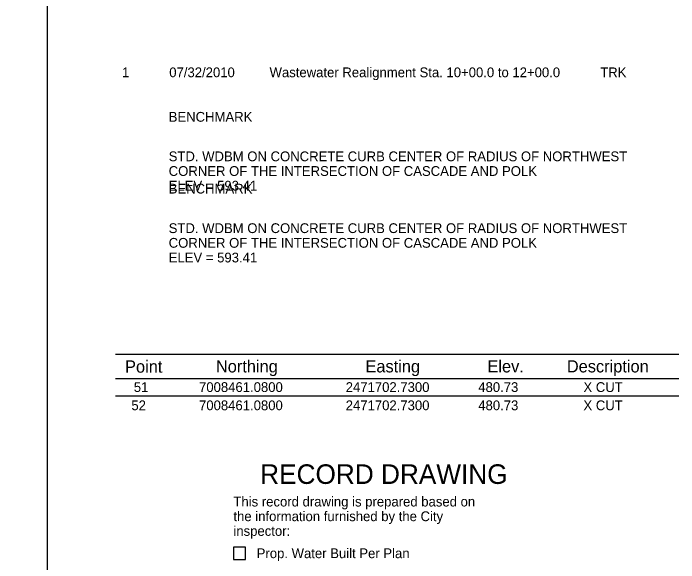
# Model space of a CAD drawing. Extents: x -3875 to -2152, y -2513 to -1536.
# Drawn here: x -2468.5 to -2196.8, y -2281.1 to -2056.6 of the extents above; entities that cross this region are included whole.
import ezdxf

# ---------------------------------------------------------------- set-up
doc = ezdxf.new("R2010")
doc.units = 0
for name, color, linetype in [('G_BORDER', 7, 'Continuous'), ('G_SHEET_EDGE', 7, 'Continuous'), ('G_SIGNATURE BLOCK', 7, 'Continuous')]:
    doc.layers.add(name, color=color, linetype=linetype)

msp = doc.modelspace()

# ---------------------------------------------------------------- linework, layer by layer
at = {"layer": 'G_BORDER'}
for p, q in [((-2426.83, -2195.84), (-2196.83, -2195.84)), ((-2426.83, -2205.84), (-2196.83, -2205.84)), ((-2426.83, -2212.84), (-2196.83, -2212.84))]:
    msp.add_line(p, q, dxfattribs=at)
at = {"layer": 'G_SHEET_EDGE'}
msp.add_lwpolyline([(-2454.61, -1582.21), (-3874.61, -1582.21), (-3874.61, -2502.21), (-2454.61, -2502.21)], close=True, dxfattribs=at)
at = {"layer": 'G_SIGNATURE BLOCK'}
msp.add_lwpolyline([(-2378.65, -2279.74), (-2373.65, -2279.74), (-2373.65, -2274.74), (-2378.65, -2274.74)], close=True, dxfattribs=at)

# ---------------------------------------------------------------- texts
at = {"layer": 'G_BORDER'}
for s, height, p in [('1', 4, (-2424.13, -2082.71)), ('07/32/2010', 4, (-2404.85, -2082.71)), ('Wastewater Realignment Sta. 10+00.0 to 12+00.0', 4, (-2363.89, -2082.71)), ('TRK', 4, (-2228.87, -2082.71)), ('BENCHMARK', 4, (-2405.08, -2100.9)), ('STD. WDBM ON CONCRETE CURB CENTER OF RADIUS OF NORTHWEST', 4, (-2405.08, -2117.04)), ('CORNER OF THE INTERSECTION OF CASCADE AND POLK', 4, (-2405.08, -2123.04)), ('ELEV = 593.41', 4, (-2405.08, -2129.04)), ('BENCHMARK', 4, (-2405.08, -2130.24)), ('STD. WDBM ON CONCRETE CURB CENTER OF RADIUS OF NORTHWEST', 4, (-2405.08, -2146.39)), ('CORNER OF THE INTERSECTION OF CASCADE AND POLK', 4, (-2405.08, -2152.39)), ('ELEV = 593.41', 4, (-2405.08, -2158.39)), ('Point', 5, (-2422.9, -2203.44)), ('Northing', 5, (-2385.8, -2203.34)), ('Easting', 5, (-2324.74, -2203.34)), ('Elev.', 5, (-2274.92, -2203.34)), ('Description', 5, (-2242.51, -2203.34)), ('51', 4, (-2419.32, -2211.34)), ('7008461.0800', 4, (-2392.69, -2211.34)), ('2471702.7300', 4, (-2332.8, -2211.34)), ('480.73', 4, (-2278.67, -2211.34)), ('X CUT', 4, (-2235.73, -2211.34)), ('52', 4, (-2420.32, -2218.79)), ('7008461.0800', 4, (-2392.69, -2218.79)), ('2471702.7300', 4, (-2332.8, -2218.79)), ('480.73', 4, (-2278.67, -2218.79)), ('X CUT', 4, (-2235.73, -2218.79))]:
    msp.add_text(s, height=height, dxfattribs=at).set_placement(p)
at = {"layer": 'G_SIGNATURE BLOCK'}
msp.add_text('RECORD DRAWING', height=8, rotation=360, dxfattribs=at).set_placement((-2367.72, -2248.9))
for s, p in [('This record drawing is prepared based on', (-2378.65, -2258.12)), ('the information furnished by the City', (-2378.65, -2264.12)), ('inspector:', (-2378.65, -2270.12)), ('Prop. Water Built Per Plan', (-2369.15, -2279.24))]:
    msp.add_text(s, height=4, dxfattribs=at).set_placement(p)

doc.saveas('drawing.dxf')
